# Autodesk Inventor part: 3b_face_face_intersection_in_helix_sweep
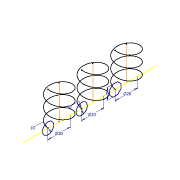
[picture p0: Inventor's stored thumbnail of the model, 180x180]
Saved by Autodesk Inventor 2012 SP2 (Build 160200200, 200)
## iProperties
Company: Autodesk, Inc.
Created: 2013-06
Part Number: 3b_face_face_intersection_in_helix_sweep
Material: Default
Document SubType Name: Modeling
Designer: Glenn Chun
Density: 1 g/cm^3
Author: Glenn Chun
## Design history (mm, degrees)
sketch "helix positions"
  geometry: L1 (0, 0)-(60, 0); L2 (60, 0)-(60, 30); L3 (60, 30)-(0, 30); L4 (0, 30)-(0, 0); L5 (30, 0)-(30, 30); 4 further points
  constraints: 10 end point, 4 point on line, 2 midpoint, 2 parallel, 1 horizontal, 1 perpendicular, 1 vertical
  dimensions: "d7" = 10 distance of point (20, 0) L5.start; "d8" = 10 distance of point (50, 0) point (60, 0); "d10" = 30 distance of L5.start L1.start; "d11" = 60 distance of point (60, 0) L1.start; "d12" = 10 distance of point (-10, 0) L1.start; "d13" = 30 distance of L1.end L2.end
sketch "Three helical paths"
  node "Helical Curve1" dims "d0" = 10, "d1" = 30, "d2" = 20, "d3" = 0
  node "Helical Curve2" dims "d14" = 10, "d15" = 30, "d16" = 20, "d17" = 0
  node "Helical Curve3" dims "d18" = 10, "d19" = 30, "d20" = 20, "d21" = 0
sketch "Profile1 (full circle)"
  geometry: C1 r 5 at (-10, 0); 1 further point
  constraints: 1 centre point, 1 coincident
  dimensions: "d22" = 10 diameter of C1
sketch "Profile2 (two circular arcs)"
  geometry: L1 (-32.04, 0)-(87.24, 0) reference; A1 r 5 centre (20, 0) between (25, 0) and (15, 0); A2 r 5 centre (20, 0) between (15, 0) and (25, 0)
  constraints: 4 point on circle, 2 centre point, 2 point on line, 1 coincident
  dimensions: "d24" = 10 diameter of A1
sketch "Profile3 (polygon)"
  geometry: L1 (45, 2.071)-(47.929, 5); L2 (47.929, 5)-(52.071, 5); L3 (52.071, 5)-(55, 2.071); L4 (55, 2.071)-(55, -2.071); L5 (55, -2.071)-(52.071, -5); L6 (52.071, -5)-(47.929, -5); L7 (47.929, -5)-(45, -2.071); L8 (45, -2.071)-(45, 2.071); L9 (-32.04, 0)-(87.24, 0) reference; 2 further points
  constraints: 16 end point, 1 coincident, 1 parallel, 17 other
  dimensions: "d26" = 10 distance between parallel lines of L6 L2
